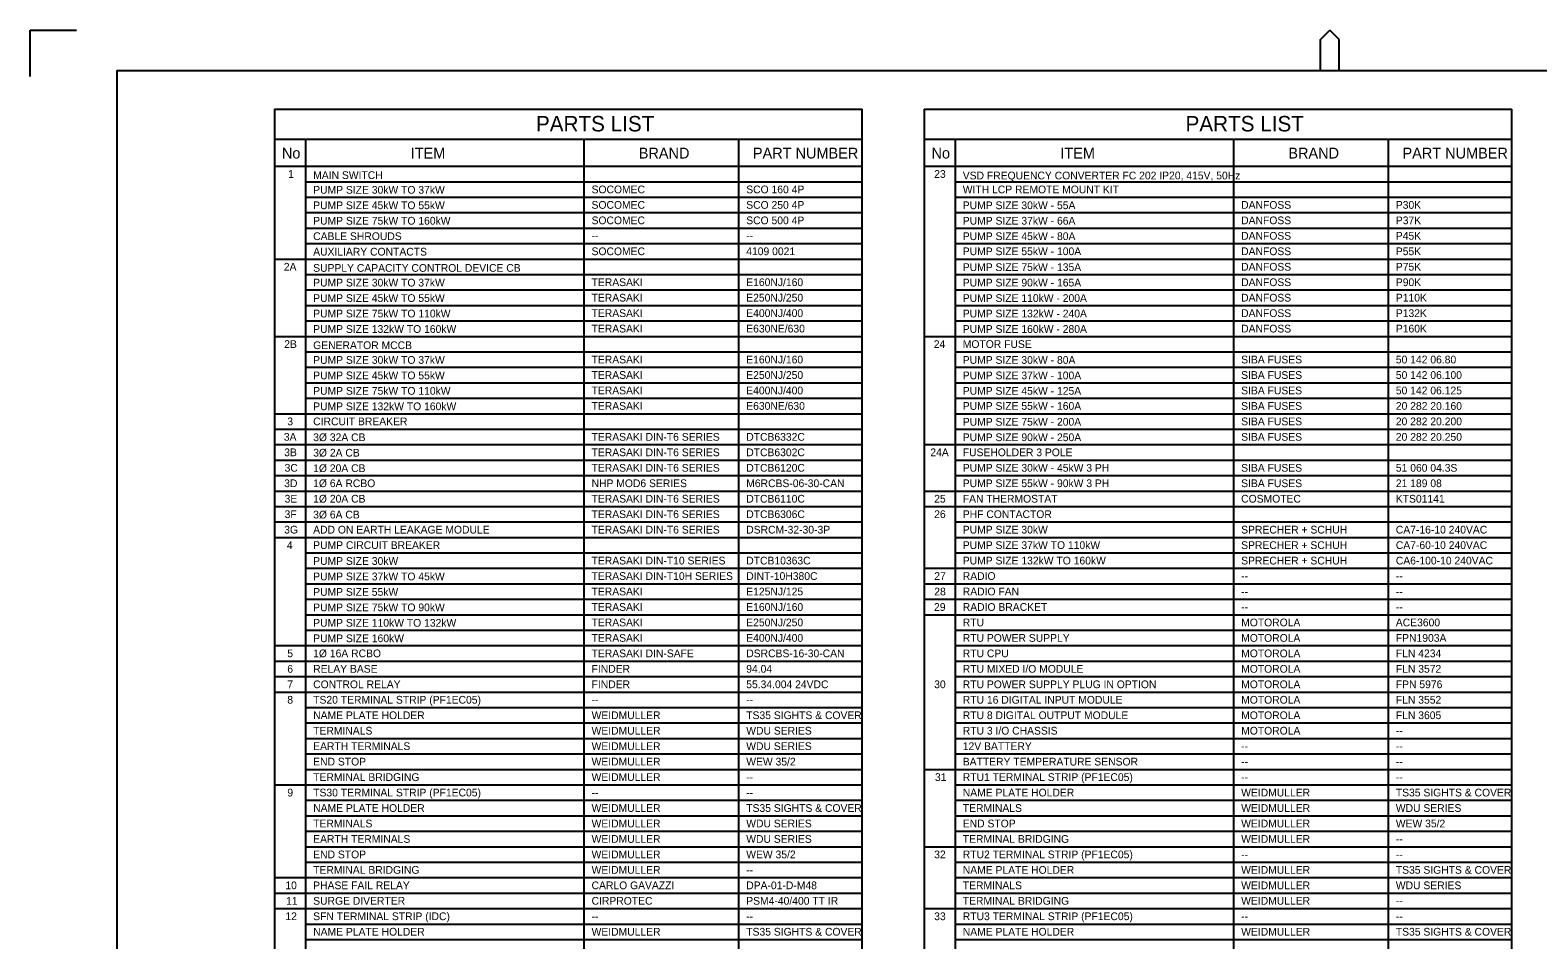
# Model space of a CAD drawing. Extents: x 841 to 1682, y 0 to 594.
# Drawn here: x 841 to 1328.4, y 299.9 to 594 of the extents above; entities that cross this region are included whole.
import ezdxf

# ---------------------------------------------------------------- set-up
doc = ezdxf.new("R2010")
doc.units = 0
for name, color, linetype in [('A1BORDER', 7, 'Continuous'), ('Default', 7, 'Continuous'), ('Level 1', 7, 'Continuous')]:
    doc.layers.add(name, color=color, linetype=linetype)

msp = doc.modelspace()

# ---------------------------------------------------------------- linework, layer by layer
at = {"layer": 'A1BORDER'}
for p, q in [((841, 594), (856, 594)), ((841, 579), (841, 594)), ((1258.19, 591), (1261.19, 594)), ((1258.19, 581), (1258.19, 591)), ((1264.19, 591), (1261.19, 594)), ((1264.19, 581), (1264.19, 591)), ((869, 581), (1670, 581)), ((869, 581), (869, 15))]:
    msp.add_line(p, q, dxfattribs=at)
at = {"layer": 'Level 1'}
for p, q in [((920, 568.5), (920, 80)), ((920, 568.5), (1110, 568.5)), ((1110, 80), (1110, 568.5)), ((1130, 568.5), (1130, 80)), ((1130, 568.5), (1320, 568.5)), ((1320, 80), (1320, 568.5)), ((920, 558.75), (1110, 558.75)), ((930, 558.75), (930, 80)), ((1020, 558.75), (1020, 80)), ((1070, 558.75), (1070, 80)), ((1130, 558.75), (1320, 558.75)), ((1140, 558.75), (1140, 80)), ((1230, 558.75), (1230, 80)), ((1280, 558.75), (1280, 80)), ((920, 550), (1110, 550)), ((1130, 550), (1320, 550)), ((930, 545), (1110, 545)), ((1140, 545), (1320, 545)), ((930, 540), (1110, 540)), ((1140, 540), (1320, 540)), ((930, 535), (1110, 535)), ((1140, 535), (1320, 535)), ((930, 530), (1110, 530)), ((1140, 530), (1320, 530)), ((930, 525), (1110, 525)), ((1140, 525), (1320, 525)), ((920, 520), (1110, 520)), ((1140, 520), (1320, 520)), ((930, 515), (1110, 515)), ((1140, 515), (1320, 515)), ((930, 510), (1110, 510)), ((1140, 510), (1320, 510)), ((930, 505), (1110, 505)), ((1140, 505), (1320, 505)), ((930, 500), (1110, 500)), ((1140, 500), (1320, 500)), ((920, 495), (1110, 495)), ((1130, 495), (1320, 495)), ((930, 490), (1110, 490)), ((1140, 490), (1320, 490)), ((930, 485), (1110, 485)), ((1140, 485), (1320, 485)), ((930, 480), (1110, 480)), ((1140, 480), (1320, 480)), ((930, 475), (1110, 475)), ((1140, 475), (1320, 475)), ((920, 470), (1110, 470)), ((1140, 470), (1320, 470)), ((920, 465), (1110, 465)), ((1140, 465), (1320, 465)), ((920, 460), (1110, 460)), ((1130, 460), (1320, 460)), ((920, 455), (1110, 455)), ((1140, 455), (1320, 455)), ((920, 450), (1110, 450)), ((1140, 450), (1320, 450)), ((920, 445), (1110, 445)), ((1130, 445), (1320, 445)), ((920, 440), (1110, 440)), ((1130, 440), (1320, 440)), ((920, 435), (1110, 435)), ((1140, 435), (1320, 435)), ((920, 430), (1110, 430)), ((1140, 430), (1320, 430)), ((930, 425), (1110, 425)), ((1140, 425), (1320, 425)), ((930, 420), (1110, 420)), ((1130, 420), (1320, 420)), ((930, 415), (1110, 415)), ((1130, 415), (1320, 415)), ((930, 410), (1110, 410)), ((1130, 410), (1320, 410)), ((930, 405), (1110, 405)), ((1130, 405), (1320, 405)), ((930, 400), (1110, 400)), ((1140, 400), (1320, 400)), ((920, 395), (1110, 395)), ((1140, 395), (1320, 395)), ((920, 390), (1110, 390)), ((1140, 390), (1320, 390)), ((920, 385), (1110, 385)), ((1140, 385), (1320, 385)), ((920, 380), (1110, 380)), ((1140, 380), (1320, 380)), ((930, 375), (1110, 375)), ((1140, 375), (1320, 375)), ((930, 370), (1110, 370)), ((1140, 370), (1320, 370)), ((930, 365), (1110, 365)), ((1140, 365), (1320, 365)), ((930, 360), (1110, 360)), ((1140, 360), (1320, 360)), ((930, 355), (1110, 355)), ((1130, 355), (1320, 355)), ((920, 350), (1110, 350)), ((1140, 350), (1320, 350)), ((930, 345), (1110, 345)), ((1140, 345), (1320, 345)), ((930, 340), (1110, 340)), ((1140, 340), (1320, 340)), ((930, 335), (1110, 335)), ((1140, 335), (1320, 335)), ((930, 330), (1110, 330)), ((1130, 330), (1320, 330)), ((930, 325), (1110, 325)), ((1140, 325), (1320, 325)), ((920, 320), (1110, 320)), ((1140, 320), (1320, 320)), ((920, 315), (1110, 315)), ((1140, 315), (1320, 315)), ((920, 310), (1110, 310)), ((1130, 310), (1320, 310)), ((930, 305), (1110, 305)), ((1140, 305), (1320, 305)), ((930, 300), (1110, 300)), ((1140, 300), (1320, 300))]:
    msp.add_line(p, q, dxfattribs=at)

# ---------------------------------------------------------------- texts
at = {"layer": 'Default'}
for s, p in [('1%%c 6A RCBO', (932.5, 446.25)), ('NHP MOD6 SERIES', (1022.5, 446.25)), ('M6RCBS-06-30-CAN', (1072.5, 446.25)), ('1Ø 20A CB', (932.5, 441.25)), ('TERASAKI DIN-T6 SERIES', (1022.5, 441.25)), ('DTCB6110C', (1072.5, 441.25)), ('CIRPROTEC', (1022.5, 311.25)), ('PSM4-40/400 TT IR', (1072.5, 311.25))]:
    msp.add_text(s, height=2.5, dxfattribs=at).set_placement(p)
at = {"layer": 'Level 1'}
for s, height, p in [('PARTS LIST', 5, (1004.515, 561.25)), ('PARTS LIST', 5, (1214.515, 561.25)), ('No', 3.5, (922.385, 552.5)), ('ITEM', 3.5, (964.043, 552.5)), ('BRAND', 3.5, (1037.753, 552.5)), ('PART NUMBER', 3.5, (1074.66, 552.5)), ('No', 3.5, (1132.385, 552.5)), ('ITEM', 3.5, (1174.043, 552.5)), ('BRAND', 3.5, (1247.753, 552.5)), ('PART NUMBER', 3.5, (1284.66, 552.5)), ('1', 2.5, (924.377, 546.25)), ('MAIN SWITCH', 2.5, (932.5, 545.877)), ('23', 2.5, (1133.257, 546.25)), ('VSD FREQUENCY CONVERTER FC 202 IP20, 415V, 50Hz', 2.5, (1142.5, 545.75)), ('PUMP SIZE 30kW TO 37kW', 2.5, (932.5, 541.125)), ('SOCOMEC', 2.5, (1022.5, 541.25)), ('SCO 160 4P', 2.5, (1072.5, 541.25)), ('WITH LCP REMOTE MOUNT KIT', 2.5, (1142.5, 541.25)), ('PUMP SIZE 45kW TO 55kW', 2.5, (932.5, 536.125)), ('SOCOMEC', 2.5, (1022.5, 536.25)), ('SCO 250 4P', 2.5, (1072.5, 536.25)), ('PUMP SIZE 30kW - 55A', 2.5, (1142.5, 536.125)), ('DANFOSS', 2.5, (1232.5, 536.25)), ('P30K', 2.5, (1282.5, 536.25)), ('PUMP SIZE 75kW TO 160kW', 2.5, (932.5, 531.125)), ('SOCOMEC', 2.5, (1022.5, 531.25)), ('SCO 500 4P', 2.5, (1072.5, 531.25)), ('PUMP SIZE 37kW - 66A', 2.5, (1142.5, 531.125)), ('DANFOSS', 2.5, (1232.5, 531.25)), ('P37K', 2.5, (1282.5, 531.25)), ('CABLE SHROUDS', 2.5, (932.5, 526.125)), ('--', 2.5, (1022.5, 526.25)), ('--', 2.5, (1072.5, 526.25)), ('PUMP SIZE 45kW - 80A', 2.5, (1142.5, 526.125)), ('DANFOSS', 2.5, (1232.5, 526.25)), ('P45K', 2.5, (1282.5, 526.25)), ('AUXILIARY CONTACTS', 2.5, (932.5, 521.125)), ('SOCOMEC', 2.5, (1022.5, 521.25)), ('4109 0021', 2.5, (1072.5, 521.25)), ('PUMP SIZE 55kW - 100A', 2.5, (1142.5, 521.25)), ('DANFOSS', 2.5, (1232.5, 521.25)), ('P55K', 2.5, (1282.5, 521.25)), ('2A', 2.5, (923.008, 516.25)), ('SUPPLY CAPACITY CONTROL DEVICE CB', 2.5, (932.5, 515.877)), ('PUMP SIZE 75kW - 135A', 2.5, (1142.5, 516.125)), ('DANFOSS', 2.5, (1232.5, 516.25)), ('P75K', 2.5, (1282.5, 516.25)), ('PUMP SIZE 30kW TO 37kW', 2.5, (932.5, 511.125)), ('TERASAKI', 2.5, (1022.5, 511.25)), ('E160NJ/160', 2.5, (1072.5, 511.25)), ('PUMP SIZE 90kW - 165A', 2.5, (1142.5, 511.125)), ('DANFOSS', 2.5, (1232.5, 511.25)), ('P90K', 2.5, (1282.5, 511.25)), ('PUMP SIZE 45kW TO 55kW', 2.5, (932.5, 506.125)), ('TERASAKI', 2.5, (1022.5, 506.25)), ('E250NJ/250', 2.5, (1072.5, 506.25)), ('PUMP SIZE 110kW - 200A', 2.5, (1142.5, 506.125)), ('DANFOSS', 2.5, (1232.5, 506.25)), ('P110K', 2.5, (1282.5, 506.25)), ('PUMP SIZE 75kW TO 110kW', 2.5, (932.5, 501.125)), ('TERASAKI', 2.5, (1022.5, 501.25)), ('E400NJ/400', 2.5, (1072.5, 501.25)), ('PUMP SIZE 132kW - 240A', 2.5, (1142.5, 501.125)), ('DANFOSS', 2.5, (1232.5, 501.25)), ('P132K', 2.5, (1282.5, 501.25)), ('PUMP SIZE 132kW TO 160kW', 2.5, (932.5, 496.125)), ('TERASAKI', 2.5, (1022.5, 496.25)), ('E630NE/630', 2.5, (1072.5, 496.25)), ('PUMP SIZE 160kW - 280A', 2.5, (1142.5, 496.125)), ('DANFOSS', 2.5, (1232.5, 496.25)), ('P160K', 2.5, (1282.5, 496.25)), ('2B', 2.5, (923.132, 491.25)), ('GENERATOR MCCB', 2.5, (932.5, 490.877)), ('24', 2.5, (1133.132, 491.25)), ('MOTOR FUSE', 2.5, (1142.5, 491.25)), ('PUMP SIZE 30kW TO 37kW', 2.5, (932.5, 486.125)), ('TERASAKI', 2.5, (1022.5, 486.25)), ('E160NJ/160', 2.5, (1072.5, 486.25)), ('PUMP SIZE 30kW - 80A', 2.5, (1142.5, 486.125)), ('SIBA FUSES', 2.5, (1232.5, 486.25)), ('50 142 06.80', 2.5, (1282.5, 486.25)), ('PUMP SIZE 45kW TO 55kW', 2.5, (932.5, 481.125)), ('TERASAKI', 2.5, (1022.5, 481.25)), ('E250NJ/250', 2.5, (1072.5, 481.25)), ('PUMP SIZE 37kW - 100A', 2.5, (1142.5, 481.125)), ('SIBA FUSES', 2.5, (1232.5, 481.25)), ('50 142 06.100', 2.5, (1282.5, 481.25)), ('PUMP SIZE 75kW TO 110kW', 2.5, (932.5, 476.125)), ('TERASAKI', 2.5, (1022.5, 476.25)), ('E400NJ/400', 2.5, (1072.5, 476.25)), ('PUMP SIZE 45kW - 125A', 2.5, (1142.5, 476.125)), ('SIBA FUSES', 2.5, (1232.5, 476.25)), ('50 142 06.125', 2.5, (1282.5, 476.25)), ('PUMP SIZE 132kW TO 160kW', 2.5, (932.5, 471.125)), ('TERASAKI', 2.5, (1022.5, 471.25)), ('E630NE/630', 2.5, (1072.5, 471.25)), ('PUMP SIZE 55kW - 160A', 2.5, (1142.5, 471.25)), ('SIBA FUSES', 2.5, (1232.5, 471.25)), ('20 282 20.160', 2.5, (1282.5, 471.25)), ('3', 2.5, (924.128, 466.25)), ('CIRCUIT BREAKER', 2.5, (932.5, 466.25)), ('PUMP SIZE 75kW - 200A', 2.5, (1142.5, 466.125)), ('SIBA FUSES', 2.5, (1232.5, 466.25)), ('20 282 20.200', 2.5, (1282.5, 466.25)), ('3A', 2.5, (923.008, 461.25)), ('3Ø 32A CB', 2.5, (932.5, 461.125)), ('TERASAKI DIN-T6 SERIES', 2.5, (1022.5, 461.25)), ('DTCB6332C', 2.5, (1072.5, 461.25)), ('PUMP SIZE 90kW - 250A', 2.5, (1142.5, 461.125)), ('SIBA FUSES', 2.5, (1232.5, 461.25)), ('20 282 20.250', 2.5, (1282.5, 461.25)), ('3B', 2.5, (923.132, 456.25)), ('3Ø 2A CB', 2.5, (932.5, 456.125)), ('TERASAKI DIN-T6 SERIES', 2.5, (1022.5, 456.25)), ('DTCB6302C', 2.5, (1072.5, 456.25)), ('24A', 2.5, (1132.012, 456.25)), ('FUSEHOLDER 3 POLE', 2.5, (1142.5, 456.25)), ('3C', 2.5, (923.257, 451.25)), ('1Ø 20A CB', 2.5, (932.5, 451.125)), ('TERASAKI DIN-T6 SERIES', 2.5, (1022.5, 451.25)), ('DTCB6120C', 2.5, (1072.5, 451.25)), ('PUMP SIZE 30kW - 45kW 3 PH', 2.5, (1142.5, 451.25)), ('SIBA FUSES', 2.5, (1232.5, 451.25)), ('51 060 04.3S', 2.5, (1282.5, 451.25)), ('3D', 2.5, (923.132, 446.25)), ('PUMP SIZE 55kW - 90kW 3 PH', 2.5, (1142.5, 446.25)), ('SIBA FUSES', 2.5, (1232.5, 446.25)), ('21 189 08', 2.5, (1282.5, 446.25)), ('3E', 2.5, (923.257, 441.25)), ('25', 2.5, (1133.257, 441.25)), ('FAN THERMOSTAT', 2.5, (1142.5, 441.25)), ('COSMOTEC', 2.5, (1232.5, 441.25)), ('KTS01141', 2.5, (1282.5, 441.25)), ('3F', 2.5, (923.257, 436.25)), ('3Ø 6A CB', 2.5, (932.5, 436.125)), ('TERASAKI DIN-T6 SERIES', 2.5, (1022.5, 436.25)), ('DTCB6306C', 2.5, (1072.5, 436.25)), ('26', 2.5, (1133.257, 436.25)), ('PHF CONTACTOR', 2.5, (1142.5, 436.25)), ('PUMP SIZE 30kW', 2.5, (1142.5, 431.25)), ('3G', 2.5, (923.132, 431.25)), ('ADD ON EARTH LEAKAGE MODULE', 2.5, (932.5, 431.25)), ('TERASAKI DIN-T6 SERIES', 2.5, (1022.5, 431.25)), ('DSRCM-32-30-3P', 2.5, (1072.5, 431.25)), ('SPRECHER + SCHUH', 2.5, (1232.5, 431.25)), ('CA7-16-10 240VAC', 2.5, (1282.5, 431.25)), ('4', 2.5, (924.004, 426.25)), ('PUMP CIRCUIT BREAKER', 2.5, (932.5, 426.25)), ('PUMP SIZE 37kW TO 110kW', 2.5, (1142.5, 426.25)), ('SPRECHER + SCHUH', 2.5, (1232.5, 426.25)), ('CA7-60-10 240VAC', 2.5, (1282.5, 426.25)), ('PUMP SIZE 30kW', 2.5, (932.5, 421.125)), ('TERASAKI DIN-T10 SERIES', 2.5, (1022.5, 421.25)), ('DTCB10363C', 2.5, (1072.5, 421.25)), ('PUMP SIZE 132kW TO 160kW', 2.5, (1142.5, 421.25)), ('SPRECHER + SCHUH', 2.5, (1232.5, 421.25)), ('CA6-100-10 240VAC', 2.5, (1282.5, 421.25)), ('PUMP SIZE 37kW TO 45kW', 2.5, (932.5, 416.125)), ('TERASAKI DIN-T10H SERIES', 2.5, (1022.5, 416.25)), ('DINT-10H380C', 2.5, (1072.5, 416.25)), ('27', 2.5, (1133.289, 416.25)), ('RADIO', 2.5, (1142.5, 416.25)), ('--', 2.5, (1232.5, 416.25)), ('--', 2.5, (1282.5, 416.25)), ('PUMP SIZE 55kW', 2.5, (932.5, 411.125)), ('TERASAKI', 2.5, (1022.5, 411.25)), ('E125NJ/125', 2.5, (1072.5, 411.25)), ('28', 2.5, (1133.289, 411.25)), ('RADIO FAN', 2.5, (1142.5, 411.25)), ('--', 2.5, (1232.5, 411.25)), ('--', 2.5, (1282.5, 411.25)), ('PUMP SIZE 75kW TO 90kW', 2.5, (932.5, 406.125)), ('TERASAKI', 2.5, (1022.5, 406.25)), ('E160NJ/160', 2.5, (1072.5, 406.25)), ('29', 2.5, (1133.213, 406.25)), ('RADIO BRACKET', 2.5, (1142.5, 406.25)), ('--', 2.5, (1232.5, 406.25)), ('--', 2.5, (1282.5, 406.25)), ('PUMP SIZE 110kW TO 132kW', 2.5, (932.5, 401.125)), ('TERASAKI', 2.5, (1022.5, 401.25)), ('E250NJ/250', 2.5, (1072.5, 401.25)), ('RTU', 2.5, (1142.5, 401.25)), ('MOTOROLA', 2.5, (1232.5, 401.25)), ('ACE3600', 2.5, (1282.5, 401.25)), ('PUMP SIZE 160kW', 2.5, (932.5, 396.125)), ('TERASAKI', 2.5, (1022.5, 396.25)), ('E400NJ/400', 2.5, (1072.5, 396.25)), ('RTU POWER SUPPLY', 2.5, (1142.5, 396.25)), ('MOTOROLA', 2.5, (1232.5, 396.25)), ('FPN1903A', 2.5, (1282.5, 396.25)), ('5', 2.5, (924.128, 391.25)), ('1%%c 16A RCBO', 2.5, (932.5, 391.25)), ('TERASAKI DIN-SAFE', 2.5, (1022.5, 391.25)), ('DSRCBS-16-30-CAN', 2.5, (1072.5, 391.25)), ('RTU CPU', 2.5, (1142.5, 391.25)), ('MOTOROLA', 2.5, (1232.5, 391.25)), ('FLN 4234', 2.5, (1282.5, 391.25)), ('6', 2.5, (924.128, 386.25)), ('RELAY BASE', 2.5, (932.5, 386.25)), ('FINDER', 2.5, (1022.5, 386.25)), ('94.04', 2.5, (1072.5, 386.25)), ('RTU MIXED I/O MODULE', 2.5, (1142.5, 386.25)), ('MOTOROLA', 2.5, (1232.5, 386.25)), ('FLN 3572', 2.5, (1282.5, 386.25)), ('7', 2.5, (924.128, 381.25)), ('CONTROL RELAY', 2.5, (932.5, 381.25)), ('FINDER', 2.5, (1022.5, 381.25)), ('55.34.004 24VDC', 2.5, (1072.5, 381.25)), ('30', 2.5, (1133.257, 381.25)), ('RTU POWER SUPPLY PLUG IN OPTION', 2.5, (1142.5, 381.25)), ('MOTOROLA', 2.5, (1232.5, 381.25)), ('FPN 5976', 2.5, (1282.5, 381.25)), ('8', 2.5, (924.128, 376.25)), ('TS20 TERMINAL STRIP (PF1EC05)', 2.5, (932.5, 376.25)), ('--', 2.5, (1022.5, 376.25)), ('--', 2.5, (1072.5, 376.25)), ('RTU 16 DIGITAL INPUT MODULE', 2.5, (1142.5, 376.25)), ('MOTOROLA', 2.5, (1232.5, 376.25)), ('FLN 3552', 2.5, (1282.5, 376.25)), ('NAME PLATE HOLDER', 2.5, (932.5, 371.25)), ('WEIDMULLER', 2.5, (1022.5, 371.25)), ('TS35 SIGHTS & COVER', 2.5, (1072.5, 371.25)), ('RTU 8 DIGITAL OUTPUT MODULE', 2.5, (1142.5, 371.25)), ('MOTOROLA', 2.5, (1232.5, 371.25)), ('FLN 3605', 2.5, (1282.5, 371.25)), ('TERMINALS', 2.5, (932.5, 366.25)), ('WEIDMULLER', 2.5, (1022.5, 366.25)), ('WDU SERIES', 2.5, (1072.5, 366.25)), ('RTU 3 I/O CHASSIS', 2.5, (1142.5, 366.25)), ('MOTOROLA', 2.5, (1232.5, 366.25)), ('--', 2.5, (1282.5, 366.25)), ('EARTH TERMINALS', 2.5, (932.5, 361.25)), ('WEIDMULLER', 2.5, (1022.5, 361.25)), ('WDU SERIES', 2.5, (1072.5, 361.25)), ('12V BATTERY', 2.5, (1142.5, 361.25)), ('--', 2.5, (1232.5, 361.25)), ('--', 2.5, (1282.5, 361.25)), ('END STOP', 2.5, (932.5, 356.25)), ('WEIDMULLER', 2.5, (1022.5, 356.25)), ('WEW 35/2', 2.5, (1072.5, 356.25)), ('BATTERY TEMPERATURE SENSOR', 2.5, (1142.5, 356.25)), ('--', 2.5, (1232.5, 356.25)), ('--', 2.5, (1282.5, 356.25)), ('TERMINAL BRIDGING', 2.5, (932.5, 351.25)), ('WEIDMULLER', 2.5, (1022.5, 351.25)), ('--', 2.5, (1072.5, 351.25)), ('31', 2.5, (1133.506, 351.25)), ('RTU1 TERMINAL STRIP (PF1EC05)', 2.5, (1142.5, 351.25)), ('--', 2.5, (1232.5, 351.25)), ('--', 2.5, (1282.5, 351.25)), ('9', 2.5, (924.142, 346.25)), ('TS30 TERMINAL STRIP (PF1EC05)', 2.5, (932.5, 346.25)), ('--', 2.5, (1022.5, 346.25)), ('--', 2.5, (1072.5, 346.25)), ('NAME PLATE HOLDER', 2.5, (1142.5, 346.25)), ('WEIDMULLER', 2.5, (1232.5, 346.25)), ('TS35 SIGHTS & COVER', 2.5, (1282.5, 346.25)), ('NAME PLATE HOLDER', 2.5, (932.5, 341.25)), ('WEIDMULLER', 2.5, (1022.5, 341.25)), ('TS35 SIGHTS & COVER', 2.5, (1072.5, 341.25)), ('TERMINALS', 2.5, (1142.5, 341.25)), ('WEIDMULLER', 2.5, (1232.5, 341.25)), ('WDU SERIES', 2.5, (1282.5, 341.25)), ('TERMINALS', 2.5, (932.5, 336.25)), ('WEIDMULLER', 2.5, (1022.5, 336.25)), ('WDU SERIES', 2.5, (1072.5, 336.25)), ('END STOP', 2.5, (1142.5, 336.25)), ('WEIDMULLER', 2.5, (1232.5, 336.25)), ('WEW 35/2', 2.5, (1282.5, 336.25)), ('EARTH TERMINALS', 2.5, (932.5, 331.25)), ('WEIDMULLER', 2.5, (1022.5, 331.25)), ('WDU SERIES', 2.5, (1072.5, 331.25)), ('TERMINAL BRIDGING', 2.5, (1142.5, 331.25)), ('WEIDMULLER', 2.5, (1232.5, 331.25)), ('--', 2.5, (1282.5, 331.25)), ('END STOP', 2.5, (932.5, 326.25)), ('WEIDMULLER', 2.5, (1022.5, 326.25)), ('WEW 35/2', 2.5, (1072.5, 326.25)), ('32', 2.5, (1133.257, 326.25)), ('RTU2 TERMINAL STRIP (PF1EC05)', 2.5, (1142.5, 326.25)), ('--', 2.5, (1232.5, 326.25)), ('--', 2.5, (1282.5, 326.25)), ('TERMINAL BRIDGING', 2.5, (932.5, 321.25)), ('WEIDMULLER', 2.5, (1022.5, 321.25)), ('--', 2.5, (1072.5, 321.25)), ('NAME PLATE HOLDER', 2.5, (1142.5, 321.25)), ('WEIDMULLER', 2.5, (1232.5, 321.25)), ('TS35 SIGHTS & COVER', 2.5, (1282.5, 321.25)), ('10', 2.5, (923.506, 316.25)), ('PHASE FAIL RELAY', 2.5, (932.5, 316.25)), ('CARLO GAVAZZI', 2.5, (1022.5, 316.25)), ('DPA-01-D-M48', 2.5, (1072.5, 316.25)), ('TERMINALS', 2.5, (1142.5, 316.25)), ('WEIDMULLER', 2.5, (1232.5, 316.25)), ('WDU SERIES', 2.5, (1282.5, 316.25)), ('11', 2.5, (923.755, 311.25)), ('SURGE DIVERTER', 2.5, (932.5, 311.25)), ('TERMINAL BRIDGING', 2.5, (1142.5, 311.25)), ('WEIDMULLER', 2.5, (1232.5, 311.25)), ('--', 2.5, (1282.5, 311.25)), ('12', 2.5, (923.506, 306.25)), ('SFN TERMINAL STRIP (IDC)', 2.5, (932.5, 306.25)), ('--', 2.5, (1022.5, 306.25)), ('--', 2.5, (1072.5, 306.25)), ('33', 2.5, (1133.257, 306.25)), ('RTU3 TERMINAL STRIP (PF1EC05)', 2.5, (1142.5, 306.25)), ('--', 2.5, (1232.5, 306.25)), ('--', 2.5, (1282.5, 306.25)), ('NAME PLATE HOLDER', 2.5, (932.5, 301.25)), ('WEIDMULLER', 2.5, (1022.5, 301.25)), ('TS35 SIGHTS & COVER', 2.5, (1072.5, 301.25)), ('NAME PLATE HOLDER', 2.5, (1142.5, 301.25)), ('WEIDMULLER', 2.5, (1232.5, 301.25)), ('TS35 SIGHTS & COVER', 2.5, (1282.5, 301.25))]:
    msp.add_text(s, height=height, dxfattribs=at).set_placement(p)

doc.saveas('drawing.dxf')
